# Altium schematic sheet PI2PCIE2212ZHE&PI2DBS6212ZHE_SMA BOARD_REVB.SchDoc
size 386 x 246 mm
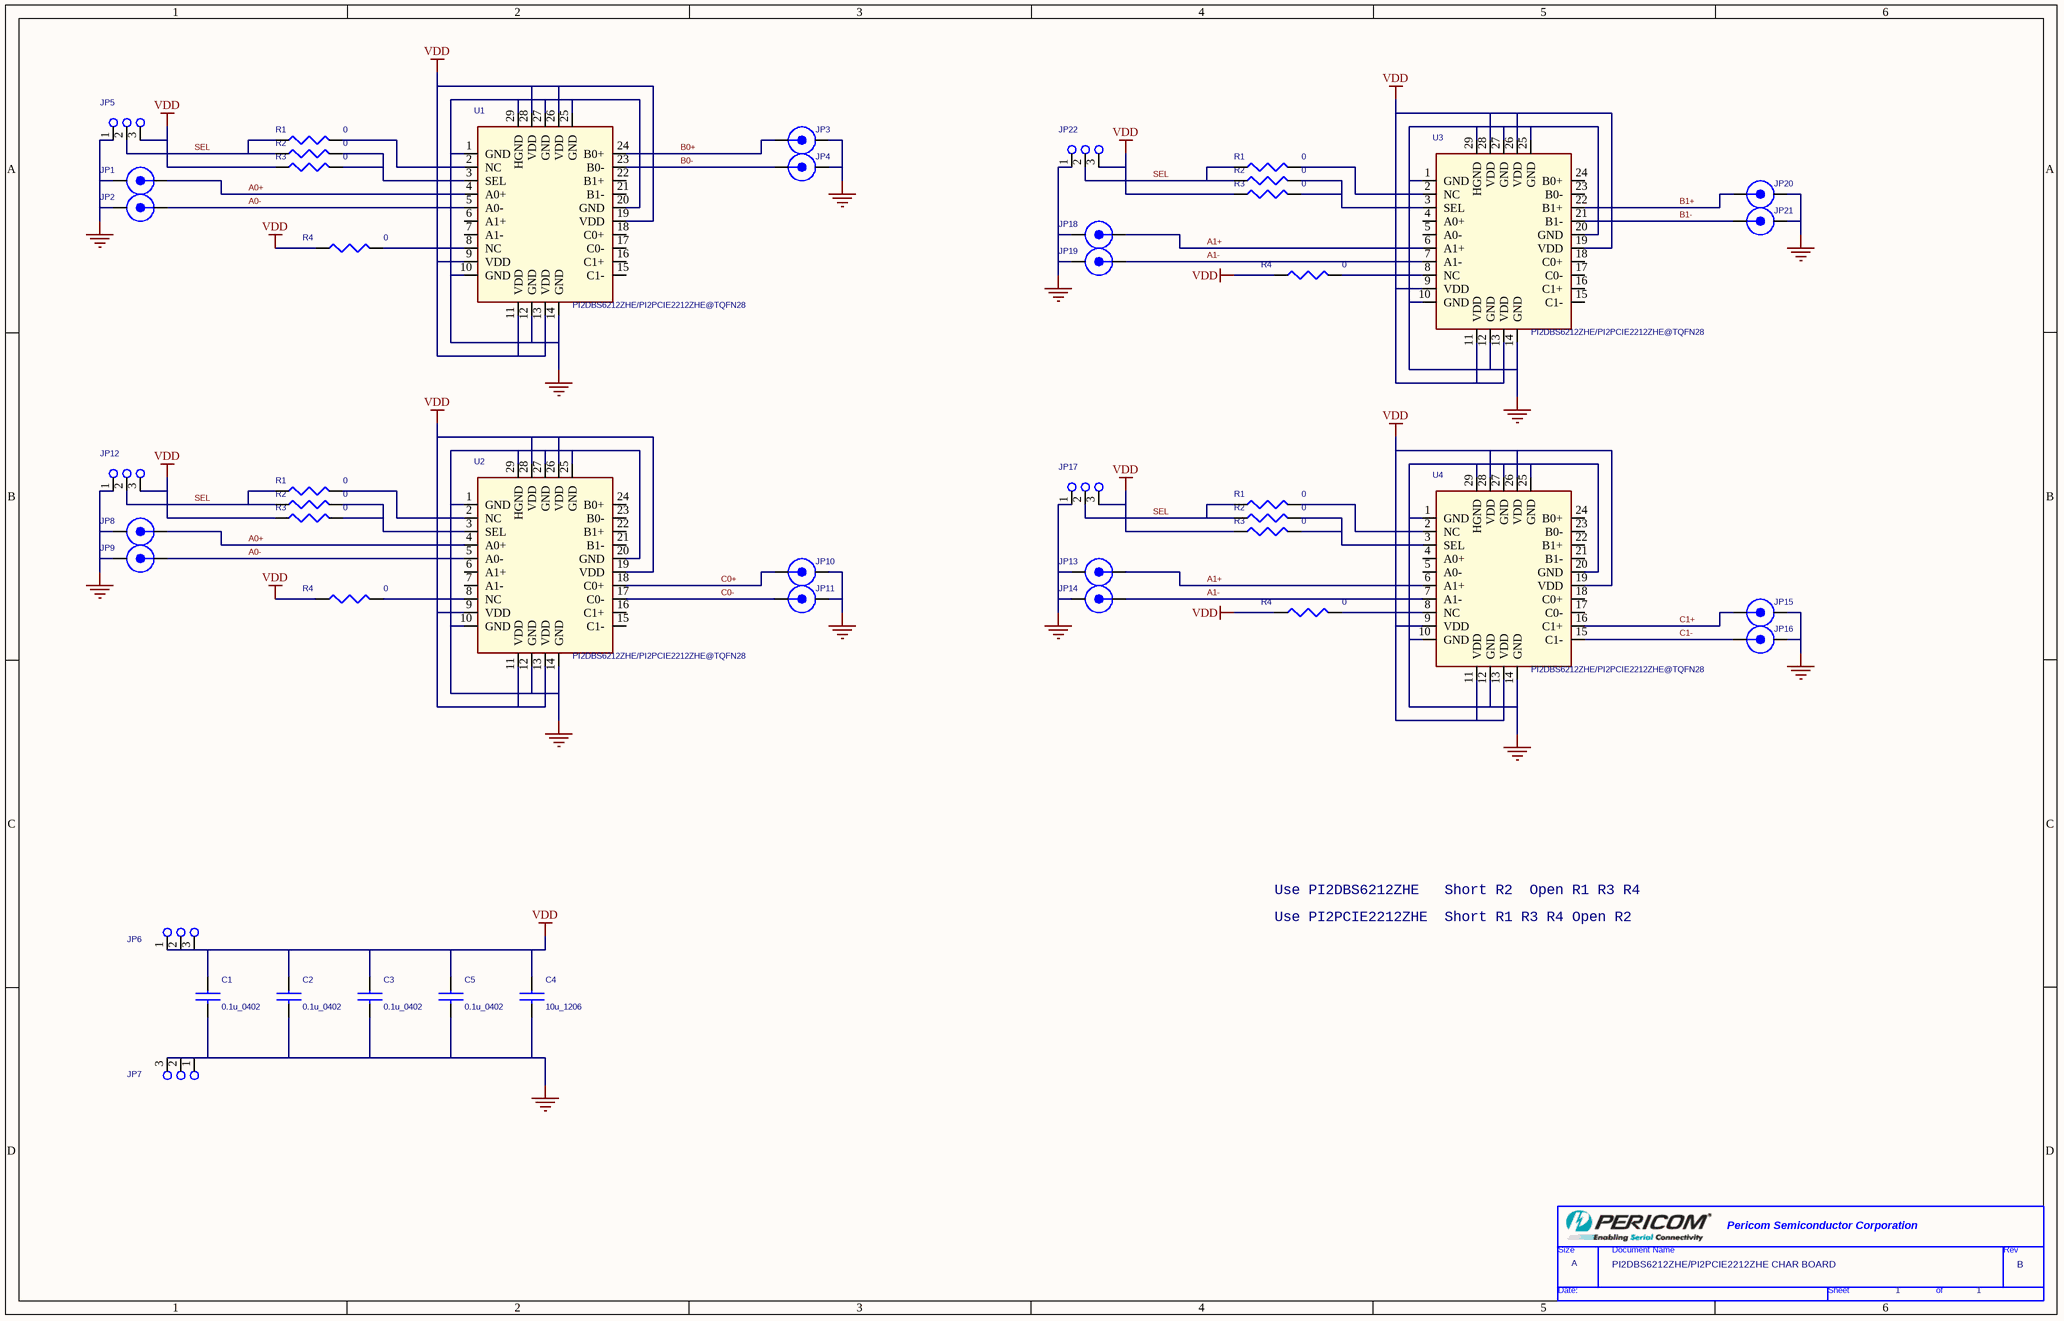
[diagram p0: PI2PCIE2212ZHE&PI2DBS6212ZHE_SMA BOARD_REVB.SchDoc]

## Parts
(Parts that share a designator on the sheet are numbered #1, #2 ... from top to bottom, then left to right.)
*  Page Count: 1  Page Size: A  RevCode: B  Doc: PI2DBS6212ZHE/PI2PCIE2212ZHE CHAR BOARD  (hidden comment: 0TitleBlock_PSC)  (graphical)
C1  0.1u_0402  [CC_0402]
C2  0.1u_0402  [CC_0402]
C3  0.1u_0402  [CC_0402]
C4  10u_1206  [CC_1206]
C5  0.1u_0402  [CC_0402]
JP1  RF_SMA_End  [RF_SMA_End]  (value not drawn)
JP2  RF_SMA_End  [RF_SMA_End]  (value not drawn)
JP3  RF_SMA_End  [RF_SMA_End]  (value not drawn)
JP4  RF_SMA_End  [RF_SMA_End]  (value not drawn)
JP5  3x1 Pin Header  [3x1 Pin Header]  (value not drawn)
JP6  3x1 Pin Header  [3x1 Pin Header]  (value not drawn)
JP7  3x1 Pin Header  [3x1 Pin Header]  (value not drawn)
JP8  RF_SMA_End  [RF_SMA_End]  (value not drawn)
JP9  RF_SMA_End  [RF_SMA_End]  (value not drawn)
JP10  RF_SMA_End  [RF_SMA_End]  (value not drawn)
JP11  RF_SMA_End  [RF_SMA_End]  (value not drawn)
JP12  3x1 Pin Header  [3x1 Pin Header]  (value not drawn)
JP13  RF_SMA_End  [RF_SMA_End]  (value not drawn)
JP14  RF_SMA_End  [RF_SMA_End]  (value not drawn)
JP15  RF_SMA_End  [RF_SMA_End]  (value not drawn)
JP16  RF_SMA_End  [RF_SMA_End]  (value not drawn)
JP17  3x1 Pin Header  [3x1 Pin Header]  (value not drawn)
JP18  RF_SMA_End  [RF_SMA_End]  (value not drawn)
JP19  RF_SMA_End  [RF_SMA_End]  (value not drawn)
JP20  RF_SMA_End  [RF_SMA_End]  (value not drawn)
JP21  RF_SMA_End  [RF_SMA_End]  (value not drawn)
JP22  3x1 Pin Header  [3x1 Pin Header]  (value not drawn)
R1#1  0  [R_0402]
R1#2  0  [R_0402]
R1#3  0  [R_0402]
R1#4  0  [R_0402]
R2#1  0  [R_0402]
R2#2  0  [R_0402]
R2#3  0  [R_0402]
R2#4  0  [R_0402]
R3#1  0  [R_0402]
R3#2  0  [R_0402]
R3#3  0  [R_0402]
R3#4  0  [R_0402]
R4#1  0  [R_0402]
R4#2  0  [R_0402]
R4#3  0  [R_0402]
R4#4  0  [R_0402]
U1  PI2DBS6212ZHE/PI2PCIE2212ZHE@TQFN28  [TQFN28]
U2  PI2DBS6212ZHE/PI2PCIE2212ZHE@TQFN28  [TQFN28]
U3  PI2DBS6212ZHE/PI2PCIE2212ZHE@TQFN28  [TQFN28]
U4  PI2DBS6212ZHE/PI2PCIE2212ZHE@TQFN28  [TQFN28]

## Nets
GND: C1.2 C2.2 C3.2 C4.2 C5.2 JP1.2 JP1.3 JP1.4 JP1.5 JP1.6 JP1.7 JP1.8 JP1.9 JP1.10 JP1.11 JP1.12 JP1.13 JP1.14 JP1.15 JP1.16 JP1.17 JP1.18 JP1.19 JP1.20 JP1.21 JP1.22 JP1.23 JP1.24 JP1.25 JP1.26 JP1.27 JP1.28 JP1.29 JP1.30 JP1.31 JP1.32 JP1.33 JP1.34 JP2.2 JP2.3 JP2.4 JP2.5 JP2.6 JP2.7 JP2.8 JP2.9 JP2.10 JP2.11 JP2.12 JP2.13 JP2.14 JP2.15 JP2.16 JP2.17 JP2.18 JP2.19 JP2.20 JP2.21 JP2.22 JP2.23 JP2.24 JP2.25 JP2.26 JP2.27 JP2.28 JP2.29 JP2.30 JP2.31 JP2.32 JP2.33 JP2.34 JP3.2 JP3.3 JP3.4 JP3.5 JP3.6 JP3.7 JP3.8 JP3.9 JP3.10 JP3.11 JP3.12 JP3.13 JP3.14 JP3.15 JP3.16 JP3.17 JP3.18 JP3.19 JP3.20 JP3.21 JP3.22 JP3.23 JP3.24 JP3.25 JP3.26 JP3.27 JP3.28 JP3.29 JP3.30 JP3.31 JP3.32 JP3.33 JP3.34 JP4.2 JP4.3 JP4.4 JP4.5 JP4.6 JP4.7 JP4.8 JP4.9 JP4.10 JP4.11 JP4.12 JP4.13 JP4.14 JP4.15 JP4.16 JP4.17 JP4.18 JP4.19 JP4.20 JP4.21 JP4.22 JP4.23 JP4.24 JP4.25 JP4.26 JP4.27 JP4.28 JP4.29 JP4.30 JP4.31 JP4.32 JP4.33 JP4.34 JP5.1 JP7.1 JP7.2 JP7.3 JP8.2 JP8.3 JP8.4 JP8.5 JP8.6 JP8.7 JP8.8 JP8.9 JP8.10 JP8.11 JP8.12 JP8.13 JP8.14 JP8.15 JP8.16 JP8.17 JP8.18 JP8.19 JP8.20 JP8.21 JP8.22 JP8.23 JP8.24 JP8.25 JP8.26 JP8.27 JP8.28 JP8.29 JP8.30 JP8.31 JP8.32 JP8.33 JP8.34 JP9.2 JP9.3 JP9.4 JP9.5 JP9.6 JP9.7 JP9.8 JP9.9 JP9.10 JP9.11 JP9.12 JP9.13 JP9.14 JP9.15 JP9.16 JP9.17 JP9.18 JP9.19 JP9.20 JP9.21 JP9.22 JP9.23 JP9.24 JP9.25 JP9.26 JP9.27 JP9.28 JP9.29 JP9.30 JP9.31 JP9.32 JP9.33 JP9.34 JP10.2 JP10.3 JP10.4 JP10.5 JP10.6 JP10.7 JP10.8 JP10.9 JP10.10 JP10.11 JP10.12 JP10.13 JP10.14 JP10.15 JP10.16 JP10.17 JP10.18 JP10.19 JP10.20 JP10.21 JP10.22 JP10.23 JP10.24 JP10.25 JP10.26 JP10.27 JP10.28 JP10.29 JP10.30 JP10.31 JP10.32 JP10.33 JP10.34 JP11.2 JP11.3 JP11.4 JP11.5 JP11.6 JP11.7 JP11.8 JP11.9 JP11.10 JP11.11 JP11.12 JP11.13 JP11.14 JP11.15 JP11.16 JP11.17 JP11.18 JP11.19 JP11.20 JP11.21 JP11.22 JP11.23 JP11.24 JP11.25 JP11.26 JP11.27 JP11.28 JP11.29 JP11.30 JP11.31 JP11.32 JP11.33 JP11.34 JP12.1 JP13.2 JP13.3 JP13.4 JP13.5 JP13.6 JP13.7 JP13.8 JP13.9 JP13.10 JP13.11 JP13.12 JP13.13 JP13.14 JP13.15 JP13.16 JP13.17 JP13.18 JP13.19 JP13.20 JP13.21 JP13.22 JP13.23 JP13.24 JP13.25 JP13.26 JP13.27 JP13.28 JP13.29 JP13.30 JP13.31 JP13.32 JP13.33 JP13.34 JP14.2 JP14.3 JP14.4 JP14.5 JP14.6 JP14.7 JP14.8 JP14.9 JP14.10 JP14.11 JP14.12 JP14.13 JP14.14 JP14.15 JP14.16 JP14.17 JP14.18 JP14.19 JP14.20 JP14.21 JP14.22 JP14.23 JP14.24 JP14.25 JP14.26 JP14.27 JP14.28 JP14.29 JP14.30 JP14.31 JP14.32 JP14.33 JP14.34 JP15.2 JP15.3 JP15.4 JP15.5 JP15.6 JP15.7 JP15.8 JP15.9 JP15.10 JP15.11 JP15.12 JP15.13 JP15.14 JP15.15 JP15.16 JP15.17 JP15.18 JP15.19 JP15.20 JP15.21 JP15.22 JP15.23 JP15.24 JP15.25 JP15.26 JP15.27 JP15.28 JP15.29 JP15.30 JP15.31 JP15.32 JP15.33 JP15.34 JP16.2 JP16.3 JP16.4 JP16.5 JP16.6 JP16.7 JP16.8 JP16.9 JP16.10 JP16.11 JP16.12 JP16.13 JP16.14 JP16.15 JP16.16 JP16.17 JP16.18 JP16.19 JP16.20 JP16.21 JP16.22 JP16.23 JP16.24 JP16.25 JP16.26 JP16.27 JP16.28 JP16.29 JP16.30 JP16.31 JP16.32 JP16.33 JP16.34 JP17.1 JP18.2 JP18.3 JP18.4 JP18.5 JP18.6 JP18.7 JP18.8 JP18.9 JP18.10 JP18.11 JP18.12 JP18.13 JP18.14 JP18.15 JP18.16 JP18.17 JP18.18 JP18.19 JP18.20 JP18.21 JP18.22 JP18.23 JP18.24 JP18.25 JP18.26 JP18.27 JP18.28 JP18.29 JP18.30 JP18.31 JP18.32 JP18.33 JP18.34 JP19.2 JP19.3 JP19.4 JP19.5 JP19.6 JP19.7 JP19.8 JP19.9 JP19.10 JP19.11 JP19.12 JP19.13 JP19.14 JP19.15 JP19.16 JP19.17 JP19.18 JP19.19 JP19.20 JP19.21 JP19.22 JP19.23 JP19.24 JP19.25 JP19.26 JP19.27 JP19.28 JP19.29 JP19.30 JP19.31 JP19.32 JP19.33 JP19.34 JP20.2 JP20.3 JP20.4 JP20.5 JP20.6 JP20.7 JP20.8 JP20.9 JP20.10 JP20.11 JP20.12 JP20.13 JP20.14 JP20.15 JP20.16 JP20.17 JP20.18 JP20.19 JP20.20 JP20.21 JP20.22 JP20.23 JP20.24 JP20.25 JP20.26 JP20.27 JP20.28 JP20.29 JP20.30 JP20.31 JP20.32 JP20.33 JP20.34 JP21.2 JP21.3 JP21.4 JP21.5 JP21.6 JP21.7 JP21.8 JP21.9 JP21.10 JP21.11 JP21.12 JP21.13 JP21.14 JP21.15 JP21.16 JP21.17 JP21.18 JP21.19 JP21.20 JP21.21 JP21.22 JP21.23 JP21.24 JP21.25 JP21.26 JP21.27 JP21.28 JP21.29 JP21.30 JP21.31 JP21.32 JP21.33 JP21.34 JP22.1 U1.1(GND) U1.10(GND) U1.12(GND) U1.14(GND) U1.20(GND) U1.25(GND) U1.27(GND) U1.29(HGND) U2.1(GND) U2.10(GND) U2.12(GND) U2.14(GND) U2.20(GND) U2.25(GND) U2.27(GND) U2.29(HGND) U3.1(GND) U3.10(GND) U3.12(GND) U3.14(GND) U3.20(GND) U3.25(GND) U3.27(GND) U3.29(HGND) U4.1(GND) U4.10(GND) U4.12(GND) U4.14(GND) U4.20(GND) U4.25(GND) U4.27(GND) U4.29(HGND)
VDD: C1.1 C2.1 C3.1 C4.1 C5.1 JP5.3 JP6.1 JP6.2 JP6.3 JP12.3 JP17.3 JP22.3 R3#1.1 R3#2.1 R3#3.1 R3#4.1 R4#1.1 R4#2.1 R4#3.1 R4#4.1 U1.9(VDD) U1.11(VDD) U1.13(VDD) U1.19(VDD) U1.26(VDD) U1.28(VDD) U2.9(VDD) U2.11(VDD) U2.13(VDD) U2.19(VDD) U2.26(VDD) U2.28(VDD) U3.9(VDD) U3.11(VDD) U3.13(VDD) U3.19(VDD) U3.26(VDD) U3.28(VDD) U4.9(VDD) U4.11(VDD) U4.13(VDD) U4.19(VDD) U4.26(VDD) U4.28(VDD)
A0+: JP1.1 JP8.1 U1.4(A0+) U2.4(A0+)
A0-: JP2.1 JP9.1 U1.5(A0-) U2.5(A0-)
A1+: JP13.1 JP18.1 U3.6(A1+) U4.6(A1+)
A1-: JP14.1 JP19.1 U3.7(A1-) U4.7(A1-)
B0+: JP3.1 U1.24(B0+)
B0-: JP4.1 U1.23(B0-)
B1+: JP20.1 U3.22(B1+)
B1-: JP21.1 U3.21(B1-)
C0+: JP10.1 U2.18(C0+)
C0-: JP11.1 U2.17(C0-)
C1+: JP15.1 U4.16(C1+)
C1-: JP16.1 U4.15(C1-)
SEL: JP5.2 JP12.2 JP17.2 JP22.2 R1#1.1 R1#2.1 R1#3.1 R1#4.1 R2#1.1 R2#2.1 R2#3.1 R2#4.1
NetR1#1_2: R1#1.2 U1.2(NC)
NetR1#2_2: R1#2.2 U3.2(NC)
NetR1#3_2: R1#3.2 U2.2(NC)
NetR1#4_2: R1#4.2 U4.2(NC)
NetR2#1_2: R2#1.2 R3#1.2 U1.3(SEL)
NetR2#2_2: R2#2.2 R3#2.2 U3.3(SEL)
NetR2#3_2: R2#3.2 R3#3.2 U2.3(SEL)
NetR2#4_2: R2#4.2 R3#4.2 U4.3(SEL)
NetR4#1_2: R4#1.2 U1.8(NC)
NetR4#2_2: R4#2.2 U3.8(NC)
NetR4#3_2: R4#3.2 U2.8(NC)
NetR4#4_2: R4#4.2 U4.8(NC)

Not connected (* = marked no-connect by the designer): U1 6(A1+) 7(A1-) 15(C1-) 16(C1+) 17(C0-) 18(C0+) 21(B1-) 22(B1+); U2 6(A1+) 7(A1-) 15(C1-) 16(C1+) 21(B1-) 22(B1+) 23(B0-) 24(B0+); U3 4(A0+) 5(A0-) 15(C1-) 16(C1+) 17(C0-) 18(C0+) 23(B0-) 24(B0+); U4 4(A0+) 5(A0-) 17(C0-) 18(C0+) 21(B1-) 22(B1+) 23(B0-) 24(B0+)

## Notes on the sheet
- Use PI2DBS6212ZHE   Short R2  Open R1 R3 R4
- Use PI2PCIE2212ZHE  Short R1 R3 R4 Open R2

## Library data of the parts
C1-C3 C5 = C_0.1u_0402
C4 = C_10u_1206
R1#1-R1#4 R2#1-R2#4 R3#1-R3#4 R4#1-R4#4 = R_0402
U1-U4 = PI2DBS6212ZHE@TQFN28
